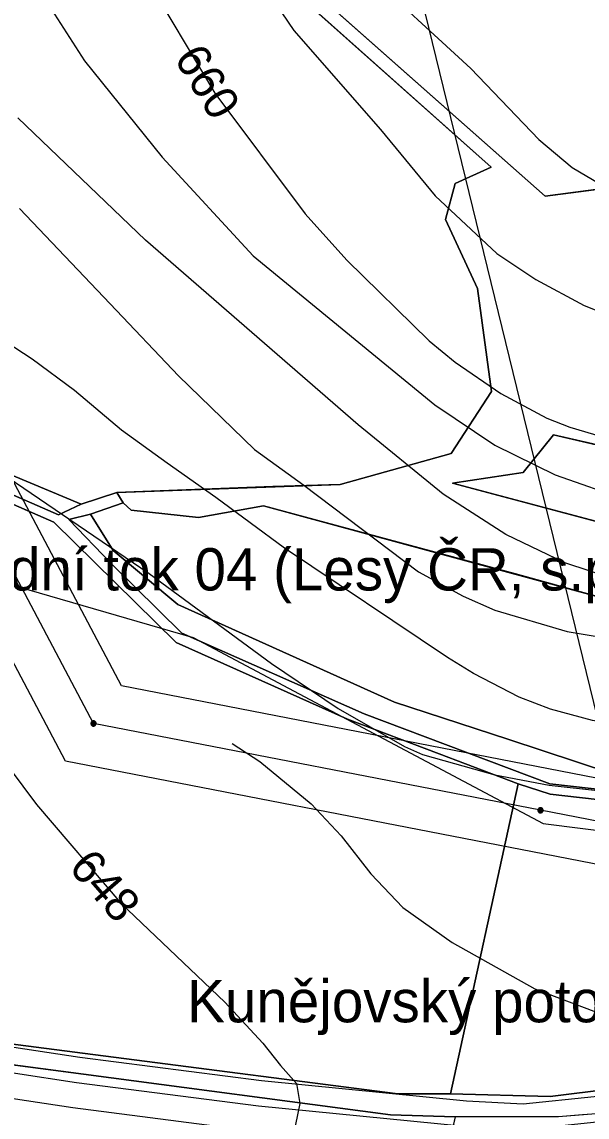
# Model space of a CAD drawing. Extents: x -709418 to -703832, y -1161719 to -1157826.
# Drawn here: x -706607.7 to -706474.1, y -1160852.4 to -1160593.4 of the extents above; entities that cross this region are included whole.
import ezdxf

# ---------------------------------------------------------------- set-up
doc = ezdxf.new("R2010")
doc.units = 0
for name, color, linetype in [('102_obvod PÚ', 7, 'Continuous'), ('120_vrstevnice hlavní', 7, 'Continuous'), ('121_vrstevnice hlavní_popis', 7, 'Continuous'), ('122_vrstevnice základní', 7, 'Continuous'), ('124_vrstevnice doplňková', 7, 'Continuous'), ('206_TTP_KN', 7, 'Continuous'), ('207_lesní pozemek_KN', 7, 'Continuous'), ('208_vodní plocha_KN', 7, 'Continuous'), ('210_ostatní plocha_KN', 7, 'Continuous'), ('501_vodní tok', 7, 'Continuous'), ('502_vodní tok_popis', 7, 'Continuous'), ('514 odvodnění - LPIS', 7, 'Continuous'), ('705_el VN nadzemní_E.ON', 7, 'Continuous'), ('723_radioreléová trasa_UAP', 7, 'Continuous'), ('735_OP sítí TI', 7, 'Continuous')]:
    doc.layers.add(name, color=color, linetype=linetype)

# ---------------------------------------------------------------- blocks, each defined once
blk = doc.blocks.new('Elektro - Implicitní$0$VN4601')
for points in [[(1.23, 0), (1.22, 0.13), (1.2, 0.26), (1.17, 0.38), (1.12, 0.5), (1.06, 0.61), (0.99, 0.72), (0.91, 0.82), (0.82, 0.91), (0.72, 0.99), (0.61, 1.06), (0.5, 1.12), (0.38, 1.17), (0.26, 1.2), (0.13, 1.22), (0, 1.23), (-0.13, 1.22), (-0.26, 1.2), (-0.38, 1.17), (-0.5, 1.12), (-0.61, 1.06), (-0.72, 0.99), (-0.82, 0.91), (-0.91, 0.82), (-0.99, 0.72), (-1.06, 0.61), (-1.12, 0.5), (-1.17, 0.38), (-1.2, 0.26), (-1.22, 0.13), (-1.23, 0), (-1.22, -0.13), (-1.2, -0.26), (-1.17, -0.38), (-1.12, -0.5), (-1.06, -0.61), (-0.99, -0.72), (-0.91, -0.82), (-0.82, -0.91), (-0.72, -0.99), (-0.61, -1.06), (-0.5, -1.12), (-0.38, -1.17), (-0.26, -1.2), (-0.13, -1.22), (0, -1.23), (0.13, -1.22), (0.26, -1.2), (0.38, -1.17), (0.5, -1.12), (0.61, -1.06), (0.72, -0.99), (0.82, -0.91), (0.91, -0.82), (0.99, -0.72), (1.06, -0.61), (1.12, -0.5), (1.17, -0.38), (1.2, -0.26), (1.22, -0.13), (1.23, 0)], [(0.92, 0), (0.92, 0.1), (0.9, 0.19), (0.88, 0.28), (0.84, 0.37), (0.8, 0.46), (0.75, 0.54), (0.68, 0.62), (0.62, 0.68), (0.54, 0.74), (0.46, 0.8), (0.37, 0.84), (0.28, 0.88), (0.19, 0.9), (0.1, 0.92), (0, 0.92), (-0.1, 0.92), (-0.19, 0.9), (-0.28, 0.88), (-0.37, 0.84), (-0.46, 0.8), (-0.54, 0.74), (-0.62, 0.68), (-0.68, 0.62), (-0.75, 0.54), (-0.8, 0.46), (-0.84, 0.37), (-0.88, 0.28), (-0.9, 0.19), (-0.92, 0.1), (-0.92, 0), (-0.92, -0.1), (-0.9, -0.19), (-0.88, -0.29), (-0.84, -0.38), (-0.8, -0.46), (-0.75, -0.54), (-0.68, -0.62), (-0.62, -0.69), (-0.54, -0.75), (-0.46, -0.8), (-0.37, -0.84), (-0.28, -0.88), (-0.19, -0.9), (-0.1, -0.92), (0, -0.92), (0.1, -0.92), (0.19, -0.9), (0.28, -0.88), (0.37, -0.84), (0.46, -0.8), (0.54, -0.75), (0.62, -0.69), (0.68, -0.62), (0.75, -0.54), (0.8, -0.46), (0.84, -0.38), (0.88, -0.29), (0.9, -0.19), (0.92, -0.1), (0.92, 0)], [(0.61, 0), (0.61, 0.06), (0.6, 0.13), (0.58, 0.19), (0.56, 0.25), (0.53, 0.31), (0.5, 0.36), (0.46, 0.41), (0.41, 0.46), (0.36, 0.5), (0.31, 0.53), (0.25, 0.56), (0.19, 0.58), (0.13, 0.6), (0.06, 0.61), (0, 0.61), (-0.06, 0.61), (-0.13, 0.6), (-0.19, 0.58), (-0.25, 0.56), (-0.31, 0.53), (-0.36, 0.5), (-0.41, 0.46), (-0.46, 0.41), (-0.5, 0.36), (-0.53, 0.31), (-0.56, 0.25), (-0.58, 0.19), (-0.6, 0.13), (-0.61, 0.06), (-0.61, 0), (-0.61, -0.07), (-0.6, -0.13), (-0.58, -0.19), (-0.56, -0.25), (-0.53, -0.31), (-0.5, -0.36), (-0.46, -0.41), (-0.41, -0.46), (-0.36, -0.5), (-0.31, -0.53), (-0.25, -0.56), (-0.19, -0.58), (-0.13, -0.6), (-0.06, -0.61), (0, -0.61), (0.06, -0.61), (0.13, -0.6), (0.19, -0.58), (0.25, -0.56), (0.31, -0.53), (0.36, -0.5), (0.41, -0.46), (0.46, -0.41), (0.5, -0.36), (0.53, -0.31), (0.56, -0.25), (0.58, -0.19), (0.6, -0.13), (0.61, -0.06), (0.61, 0)], [(0.31, 0), (0.31, 0.03), (0.3, 0.06), (0.29, 0.09), (0.28, 0.12), (0.27, 0.15), (0.25, 0.18), (0.23, 0.21), (0.21, 0.23), (0.18, 0.25), (0.15, 0.27), (0.12, 0.28), (0.09, 0.29), (0.06, 0.3), (0.03, 0.31), (0, 0.31), (-0.03, 0.31), (-0.06, 0.3), (-0.09, 0.29), (-0.12, 0.28), (-0.15, 0.27), (-0.18, 0.25), (-0.21, 0.23), (-0.23, 0.21), (-0.25, 0.18), (-0.27, 0.15), (-0.28, 0.12), (-0.29, 0.09), (-0.3, 0.06), (-0.31, 0.03), (-0.31, 0), (-0.31, -0.03), (-0.3, -0.06), (-0.29, -0.1), (-0.28, -0.13), (-0.27, -0.15), (-0.25, -0.18), (-0.23, -0.21), (-0.21, -0.23), (-0.18, -0.25), (-0.15, -0.27), (-0.12, -0.28), (-0.09, -0.29), (-0.06, -0.3), (-0.03, -0.31), (0, -0.31), (0.03, -0.31), (0.06, -0.3), (0.09, -0.29), (0.12, -0.28), (0.15, -0.27), (0.18, -0.25), (0.21, -0.23), (0.23, -0.21), (0.25, -0.18), (0.27, -0.15), (0.28, -0.13), (0.29, -0.1), (0.3, -0.06), (0.31, -0.03), (0.31, 0)]]:
    blk.add_lwpolyline(points)

msp = doc.modelspace()

# ---------------------------------------------------------------- linework, layer by layer
at = {"layer": '102_obvod PÚ'}
for points in [[(-706585.3, -1160704.67), (-706532.43, -1160702.83), (-706506.18, -1160695.47), (-706496.69, -1160680.82), (-706499.95, -1160656.47), (-706507.52, -1160640.12), (-706505.26, -1160631.63), (-706496.76, -1160627.81), (-706561.66, -1160569.9)], [(-706561.66, -1160569.9), (-706496.76, -1160627.81), (-706505.26, -1160631.63), (-706507.52, -1160640.12), (-706499.95, -1160656.47), (-706496.69, -1160680.82), (-706506.18, -1160695.47), (-706532.43, -1160702.83), (-706585.3, -1160704.67)], [(-706537.25, -1160587.47), (-706483.95, -1160634.67), (-706437.33, -1160628.53), (-706435.81, -1160625.24), (-706446.25, -1160609.53), (-706405.71, -1160604.59), (-706388.94, -1160609.69), (-706404.23, -1160630.57), (-706399.98, -1160652.01), (-706415.48, -1160655.34), (-706426.59, -1160662.98), (-706421.4, -1160677.36), (-706353.84, -1160665.92), (-706212.91, -1160642.8), (-706210.48, -1160628.13), (-706190.31, -1160626.07), (-706166.67, -1160638.53), (-706094.84, -1160616.38)], [(-706094.84, -1160616.38), (-706166.67, -1160638.53), (-706190.31, -1160626.07), (-706210.48, -1160628.13), (-706212.91, -1160642.8), (-706353.84, -1160665.92), (-706421.4, -1160677.36), (-706426.59, -1160662.98), (-706415.48, -1160655.34), (-706399.98, -1160652.01), (-706404.23, -1160630.57), (-706388.94, -1160609.69), (-706405.71, -1160604.59), (-706446.25, -1160609.53), (-706435.81, -1160625.24), (-706437.33, -1160628.53), (-706483.95, -1160634.67), (-706537.25, -1160587.47)], [(-706078.84, -1160616.17), (-706172.32, -1160644.88), (-706186.83, -1160645.94), (-706180.3, -1160673), (-706202.87, -1160669.67), (-706205.21, -1160662.52), (-706201.46, -1160647.52), (-706309.32, -1160662.59), (-706417.2, -1160682.29), (-706421.21, -1160690.13), (-706440.11, -1160691.54), (-706447.05, -1160699.18), (-706482.01, -1160691.05), (-706489.16, -1160699.96), (-706505.86, -1160702.51), (-706452.64, -1160716.67), (-706455.75, -1160733.65), (-706550.59, -1160707.82), (-706565.95, -1160710.65), (-706581.87, -1160708.88), (-706583.78, -1160707.11), (-706585.3, -1160704.67)], [(-706585.3, -1160704.67), (-706583.78, -1160707.11), (-706581.87, -1160708.88), (-706565.95, -1160710.65), (-706550.59, -1160707.82), (-706455.75, -1160733.65), (-706452.64, -1160716.67), (-706505.86, -1160702.51), (-706489.16, -1160699.96), (-706482.01, -1160691.05), (-706447.05, -1160699.18), (-706440.11, -1160691.54), (-706421.21, -1160690.13), (-706417.2, -1160682.29), (-706309.32, -1160662.59), (-706201.46, -1160647.52), (-706205.21, -1160662.52), (-706202.87, -1160669.67), (-706180.3, -1160673), (-706186.83, -1160645.94), (-706172.32, -1160644.88), (-706078.84, -1160616.17)], [(-706132.64, -1160763.73), (-706186.11, -1160775.01), (-706211.95, -1160782.93), (-706228.36, -1160784.79), (-706284.52, -1160780.59), (-706285.11, -1160766.44), (-706317.29, -1160776.61), (-706343.44, -1160778.04), (-706343.3, -1160802.68), (-706355.36, -1160805.32), (-706354.93, -1160815.6), (-706354.36, -1160827.87), (-706344.72, -1160825.16), (-706297.34, -1160821.34), (-706288.53, -1160820.63), (-706288.78, -1160824.8), (-706344.65, -1160829.16), (-706368.79, -1160838.42), (-706446.04, -1160849.6), (-706472.94, -1160851.67), (-706480.86, -1160852.31), (-706505.26, -1160852.31), (-706520.68, -1160919.75)]]:
    msp.add_lwpolyline(points, dxfattribs=at)
at = {"layer": '120_vrstevnice hlavní'}
for points in [[(-706575.65, -1160587.5), (-706562.11, -1160610.3), (-706540.74, -1160638.8), (-706530.91, -1160649.77), (-706511.38, -1160668.87), (-706505.26, -1160673.86), (-706494.43, -1160681.27), (-706483.6, -1160687.11), (-706478.18, -1160689.25), (-706461.94, -1160694.09), (-706451.11, -1160695.09), (-706445.6, -1160694.97), (-706439.71, -1160694.09), (-706430.47, -1160691.96), (-706421.75, -1160688.53), (-706396.39, -1160674.85), (-706357.77, -1160650.77), (-706347.51, -1160645.93), (-706341.96, -1160643.93)], [(-706620.39, -1160694.8), (-706577.64, -1160723.87), (-706548.72, -1160745.1), (-706532.9, -1160755.79), (-706517.22, -1160764.77), (-706512.95, -1160766.62), (-706495.85, -1160771.46), (-706483.03, -1160773.89), (-706470.2, -1160775.31), (-706434.29, -1160775.6), (-706385.85, -1160773.03), (-706367.61, -1160773.6), (-706350.51, -1160776.17), (-706341.96, -1160778.3)]]:
    msp.add_lwpolyline(points, dxfattribs=at)
at = {"layer": '122_vrstevnice základní'}
for points in [[(-706558.26, -1160573.54), (-706543.44, -1160595.48), (-706522.93, -1160618.85), (-706509.96, -1160634.53), (-706495.42, -1160648.21), (-706486.16, -1160654.33), (-706474.76, -1160660.46), (-706457.66, -1160667.3), (-706449.11, -1160669.44), (-706437.71, -1160670.72), (-706431.73, -1160670.44), (-706425.46, -1160669.3), (-706416.05, -1160665.88), (-706403.37, -1160657.04), (-706373.45, -1160630.25), (-706362.67, -1160623.11), (-706348.8, -1160618.14), (-706339.39, -1160615.86)], [(-706527.63, -1160580.38), (-706501.55, -1160604.46), (-706485.45, -1160621.28), (-706477.61, -1160627.83), (-706466.21, -1160634.53), (-706450.25, -1160641.22), (-706445.69, -1160642.51), (-706438.85, -1160643.36), (-706429.14, -1160643.21), (-706423.59, -1160642.35), (-706417.76, -1160640.51), (-706412.35, -1160637.8), (-706407.79, -1160634.24), (-706401.38, -1160626.26), (-706396.96, -1160617.71), (-706391.12, -1160609.16), (-706386.46, -1160604.18), (-706382.28, -1160600.9), (-706376.44, -1160597.05), (-706366.47, -1160592.63)], [(-706605, -1160583.8), (-706592.89, -1160602.61), (-706574.51, -1160625.41), (-706552.99, -1160648.78), (-706510.1, -1160683.97), (-706495.85, -1160693.52), (-706481.6, -1160700.5), (-706464.5, -1160706.49), (-706453.1, -1160708.34), (-706444.27, -1160708.34), (-706431.73, -1160707.2), (-706416.05, -1160704.35), (-706400.38, -1160699.93), (-706372.17, -1160689.81), (-706341.1, -1160676.99)], [(-706334.03, -1160702.99), (-706343.67, -1160705.06), (-706365.61, -1160711.47), (-706379.58, -1160716.18), (-706411.49, -1160724.3), (-706421.47, -1160726.29), (-706433.44, -1160727.86), (-706438.09, -1160728.08), (-706447.4, -1160728.15), (-706453.39, -1160727.72), (-706467.35, -1160725.3), (-706479.32, -1160721.31), (-706493.29, -1160714.61), (-706508.11, -1160705.06), (-706528.2, -1160688.68), (-706578.5, -1160645.07), (-706608.71, -1160616.15)], [(-706608.28, -1160637.52), (-706586.87, -1160660.09), (-706570.66, -1160677.13), (-706552.71, -1160694.52), (-706541.02, -1160702.93), (-706513.95, -1160723.44), (-706503.38, -1160729.2), (-706495.85, -1160732.56), (-706478.75, -1160737.55), (-706465.07, -1160739.83), (-706443.41, -1160741.11), (-706426.84, -1160740.36), (-706418.9, -1160739.55), (-706375.59, -1160734.7), (-706357.35, -1160731), (-706339.11, -1160728.43)], [(-706324, -1160754.51), (-706361.62, -1160750.52), (-706371.9, -1160750.02), (-706383.85, -1160750.23), (-706399.24, -1160752.23), (-706438.57, -1160758.93), (-706452.25, -1160760.06), (-706464.22, -1160759.92), (-706472.77, -1160758.64), (-706482.69, -1160755.91), (-706490.15, -1160753.08), (-706500.92, -1160747.51), (-706507.11, -1160743.68), (-706545.58, -1160717.89), (-706561.83, -1160705.92), (-706573.37, -1160697.8), (-706584.2, -1160689.96), (-706595.31, -1160680.55), (-706605.29, -1160673.14), (-706656.59, -1160639.66)], [(-706617.01, -1160761.43), (-706604.29, -1160778.45), (-706584.34, -1160801.82), (-706559.69, -1160825.19), (-706550.71, -1160834.87), (-706546.58, -1160840.15)], [(-706546.58, -1160840.15), (-706542.78, -1160844.42), (-706541.99, -1160849.16), (-706544.64, -1160862.2), (-706548.72, -1160880.47), (-706555.13, -1160885.17), (-706561.4, -1160887.88), (-706570.8, -1160889.88), (-706580.21, -1160890.45), (-706602.15, -1160889.59), (-706664.85, -1160882.9), (-706677.29, -1160882.43), (-706689.93, -1160882.9), (-706702.47, -1160884.32), (-706718.14, -1160887.31), (-706743.22, -1160894.01), (-706765.17, -1160899), (-706783.97, -1160900.28), (-706800.73, -1160898.5)]]:
    msp.add_lwpolyline(points, dxfattribs=at)
at = {"layer": '124_vrstevnice doplňková'}
msp.add_lwpolyline([(-706558.01, -1160764.02), (-706551.42, -1160768.33), (-706539.31, -1160778.3), (-706532.19, -1160785.86), (-706525.21, -1160794.83), (-706517.65, -1160802.81), (-706505.97, -1160811.08), (-706486.45, -1160822.05), (-706472.48, -1160827.32), (-706461.67, -1160830.53), (-706453.13, -1160833.79), (-706449.11, -1160836.3), (-706442.42, -1160840.72), (-706436.19, -1160847.18), (-706433.82, -1160851.92), (-706434.25, -1160859.11)], dxfattribs=at)
at = {"layer": '206_TTP_KN'}
for p, q in [((-706561.66, -1160569.9), (-706496.76, -1160627.81)), ((-706496.76, -1160627.81), (-706505.26, -1160631.63)), ((-706505.26, -1160631.63), (-706507.52, -1160640.12)), ((-706507.52, -1160640.12), (-706499.95, -1160656.47)), ((-706499.95, -1160656.47), (-706496.69, -1160680.82)), ((-706593.72, -1160707.46), (-706663.56, -1160678.25)), ((-706496.69, -1160680.82), (-706506.18, -1160695.47)), ((-706660.96, -1160685.35), (-706600.17, -1160711.68)), ((-706489.16, -1160699.96), (-706482.01, -1160691.05)), ((-706482.01, -1160691.05), (-706447.05, -1160699.18)), ((-706506.18, -1160695.47), (-706532.43, -1160702.83)), ((-706505.86, -1160702.51), (-706489.16, -1160699.96)), ((-706548.36, -1160703.25), (-706585.3, -1160704.67)), ((-706532.43, -1160702.83), (-706548.36, -1160703.25)), ((-706452.64, -1160716.67), (-706505.86, -1160702.51)), ((-706585.3, -1160704.67), (-706593.72, -1160707.46)), ((-706591.5, -1160709.84), (-706583.78, -1160707.11)), ((-706583.78, -1160707.11), (-706581.87, -1160708.88)), ((-706565.95, -1160710.65), (-706550.59, -1160707.82)), ((-706550.59, -1160707.82), (-706491, -1160723.96)), ((-706586.15, -1160718.38), (-706591.5, -1160709.84)), ((-706581.87, -1160708.88), (-706565.95, -1160710.65)), ((-706600.17, -1160711.68), (-706571.25, -1160740.13)), ((-706570.86, -1160731.19), (-706586.15, -1160718.38)), ((-706491, -1160723.96), (-706455.75, -1160733.65)), ((-706519.64, -1160754.25), (-706570.86, -1160731.19)), ((-706571.25, -1160740.13), (-706530.7, -1160758.32)), ((-706492.81, -1160763.05), (-706519.64, -1160754.25)), ((-706530.7, -1160758.32), (-706509.04, -1160766.53)), ((-706461.39, -1160773.42), (-706492.81, -1160763.05)), ((-706509.04, -1160766.53), (-706490.36, -1160773.6)), ((-706490.36, -1160773.6), (-706506.4, -1160846.9)), ((-706586.02, -1160838.2), (-706621.71, -1160833.58)), ((-706635.46, -1160836.75), (-706593.13, -1160842.2)), ((-706518.79, -1160846.9), (-706586.02, -1160838.2)), ((-706593.13, -1160842.2), (-706520.52, -1160851.82)), ((-706506.4, -1160846.9), (-706518.79, -1160846.9)), ((-706505.26, -1160852.31), (-706520.68, -1160919.75)), ((-706520.52, -1160851.82), (-706505.26, -1160852.31))]:
    msp.add_line(p, q, dxfattribs=at)
msp.add_lwpolyline([(-706094.84, -1160616.38), (-706166.67, -1160638.53), (-706190.31, -1160626.07), (-706210.48, -1160628.13), (-706212.91, -1160642.8), (-706353.84, -1160665.92), (-706421.4, -1160677.36), (-706426.59, -1160662.98), (-706415.48, -1160655.34), (-706399.98, -1160652.01), (-706404.23, -1160630.57), (-706388.94, -1160609.69), (-706405.71, -1160604.59), (-706446.25, -1160609.53), (-706435.81, -1160625.24), (-706437.33, -1160628.53), (-706483.95, -1160634.67), (-706537.25, -1160587.47)], dxfattribs=at)
at = {"layer": '207_lesní pozemek_KN'}
for p, q in [((-706496.76, -1160627.81), (-706561.66, -1160569.9)), ((-706537.25, -1160587.47), (-706483.95, -1160634.67)), ((-706505.26, -1160631.63), (-706496.76, -1160627.81)), ((-706483.95, -1160634.67), (-706437.33, -1160628.53)), ((-706507.52, -1160640.12), (-706505.26, -1160631.63)), ((-706499.95, -1160656.47), (-706507.52, -1160640.12)), ((-706496.69, -1160680.82), (-706499.95, -1160656.47)), ((-706506.18, -1160695.47), (-706496.69, -1160680.82)), ((-706482.01, -1160691.05), (-706489.16, -1160699.96)), ((-706447.05, -1160699.18), (-706482.01, -1160691.05)), ((-706532.43, -1160702.83), (-706506.18, -1160695.47)), ((-706489.16, -1160699.96), (-706505.86, -1160702.51)), ((-706585.3, -1160704.67), (-706548.36, -1160703.25)), ((-706548.36, -1160703.25), (-706532.43, -1160702.83)), ((-706505.86, -1160702.51), (-706452.64, -1160716.67)), ((-706583.78, -1160707.11), (-706585.3, -1160704.67)), ((-706581.87, -1160708.88), (-706583.78, -1160707.11)), ((-706550.59, -1160707.82), (-706565.95, -1160710.65)), ((-706491, -1160723.96), (-706550.59, -1160707.82)), ((-706565.95, -1160710.65), (-706581.87, -1160708.88)), ((-706455.75, -1160733.65), (-706491, -1160723.96))]:
    msp.add_line(p, q, dxfattribs=at)
at = {"layer": '208_vodní plocha_KN'}
for p, q in [((-706621.71, -1160833.58), (-706586.02, -1160838.2)), ((-706593.13, -1160842.2), (-706635.46, -1160836.75)), ((-706586.02, -1160838.2), (-706518.79, -1160846.9)), ((-706482.83, -1160847.47), (-706392.37, -1160836.66)), ((-706520.52, -1160851.82), (-706593.13, -1160842.2)), ((-706518.79, -1160846.9), (-706506.4, -1160846.9)), ((-706506.4, -1160846.9), (-706482.83, -1160847.47)), ((-706505.26, -1160852.31), (-706520.52, -1160851.82)), ((-706480.86, -1160852.31), (-706505.26, -1160852.31)), ((-706475.18, -1160851.85), (-706480.86, -1160852.31)), ((-706472.94, -1160851.67), (-706475.18, -1160851.85))]:
    msp.add_line(p, q, dxfattribs=at)
at = {"layer": '210_ostatní plocha_KN'}
for p, q in [((-706663.56, -1160678.25), (-706593.72, -1160707.46)), ((-706661.67, -1160682.8), (-706599.03, -1160709.98)), ((-706599.03, -1160709.98), (-706661.67, -1160682.8)), ((-706600.17, -1160711.68), (-706660.96, -1160685.35)), ((-706593.72, -1160707.46), (-706585.3, -1160704.67)), ((-706585.3, -1160704.67), (-706583.78, -1160707.11)), ((-706599.03, -1160709.98), (-706593.72, -1160707.46)), ((-706593.72, -1160707.46), (-706599.03, -1160709.98)), ((-706583.78, -1160707.11), (-706591.5, -1160709.84)), ((-706591.5, -1160709.84), (-706596.59, -1160711.11)), ((-706596.59, -1160711.11), (-706591.5, -1160709.84)), ((-706596.59, -1160711.11), (-706586.61, -1160721.51)), ((-706586.61, -1160721.51), (-706596.59, -1160711.11)), ((-706591.5, -1160709.84), (-706586.15, -1160718.38)), ((-706571.25, -1160740.13), (-706600.17, -1160711.68)), ((-706586.15, -1160718.38), (-706570.86, -1160731.19)), ((-706586.61, -1160721.51), (-706569.91, -1160738)), ((-706569.91, -1160738), (-706586.61, -1160721.51)), ((-706570.86, -1160731.19), (-706519.64, -1160754.25)), ((-706569.91, -1160738), (-706526.76, -1160757.02)), ((-706526.76, -1160757.02), (-706569.91, -1160738)), ((-706530.7, -1160758.32), (-706571.25, -1160740.13)), ((-706519.64, -1160754.25), (-706492.81, -1160763.05)), ((-706526.76, -1160757.02), (-706482.86, -1160773.55)), ((-706482.86, -1160773.55), (-706526.76, -1160757.02)), ((-706509.04, -1160766.53), (-706530.7, -1160758.32)), ((-706492.81, -1160763.05), (-706461.39, -1160773.42)), ((-706490.36, -1160773.6), (-706509.04, -1160766.53)), ((-706482.86, -1160773.55), (-706424.8, -1160780.15)), ((-706424.8, -1160780.15), (-706482.86, -1160773.55)), ((-706506.4, -1160846.9), (-706490.36, -1160773.6)), ((-706482.83, -1160776.06), (-706490.36, -1160773.6)), ((-706490.36, -1160773.6), (-706482.83, -1160776.06)), ((-706424.8, -1160782.5), (-706482.83, -1160776.06)), ((-706482.83, -1160776.06), (-706424.8, -1160782.5)), ((-706392.37, -1160836.66), (-706482.83, -1160847.47)), ((-706482.83, -1160847.47), (-706506.4, -1160846.9))]:
    msp.add_line(p, q, dxfattribs=at)
at = {"layer": '501_vodní tok'}
msp.add_lwpolyline([(-706294.74, -1160832), (-706344.96, -1160836.67), (-706361.92, -1160838.95), (-706380.23, -1160840.97), (-706402.58, -1160842.99), (-706419.81, -1160844.75), (-706434.62, -1160847.79), (-706456.43, -1160852.08), (-706471.78, -1160853.59), (-706489.01, -1160855.36), (-706503.02, -1160854.6), (-706551.76, -1160849.8), (-706594.84, -1160844.25), (-706638.19, -1160837.68), (-706729.87, -1160806.74), (-706754.65, -1160798.66), (-706775.37, -1160792.42), (-706776.87, -1160792.14)], dxfattribs=at)
at = {"layer": '514 odvodnění - LPIS'}
msp.add_lwpolyline([(-706863.97, -1160871.89), (-706791.27, -1160822.65), (-706735.19, -1160778.33), (-706748.47, -1160726.66), (-706643.11, -1160716.97), (-706567.25, -1160738.96), (-706484.44, -1160782.97), (-706418.79, -1160791.25), (-706025.59, -1160715.24)], dxfattribs=at)
at = {"layer": '705_el VN nadzemní_E.ON'}
msp.add_lwpolyline([(-706126.79, -1160947.26), (-706166.94, -1160904.58), (-706239.08, -1160827.82), (-706352.93, -1160805.53), (-706485.08, -1160779.84), (-706590.79, -1160759.31), (-706626.96, -1160690.96), (-706657.04, -1160633.68)], dxfattribs=at)
at = {"layer": '723_radioreléová trasa_UAP'}
msp.add_lwpolyline([(-707182.2, -1157850.62), (-706271.36, -1161577.76)], dxfattribs=at)
at = {"layer": '735_OP sítí TI'}
for points in [[(-706119.51, -1160940.41), (-706159.66, -1160897.73), (-706234, -1160818.62), (-706351.01, -1160795.71), (-706483.17, -1160770.02), (-706584.19, -1160750.4), (-706618.11, -1160686.3), (-706648.19, -1160629.03)], [(-706134.08, -1160954.11), (-706174.22, -1160911.43), (-706244.16, -1160837.01), (-706354.84, -1160815.34), (-706486.99, -1160789.66), (-706597.39, -1160768.21), (-706635.81, -1160695.62), (-706665.89, -1160638.33)], [(-706294.18, -1160837.97), (-706344.28, -1160842.63), (-706361.19, -1160844.9), (-706379.63, -1160846.94), (-706402, -1160848.96), (-706418.9, -1160850.69), (-706433.44, -1160853.67), (-706455.56, -1160858.02), (-706471.18, -1160859.56), (-706488.87, -1160861.38), (-706503.47, -1160860.59), (-706552.43, -1160855.77), (-706595.67, -1160850.19), (-706639.61, -1160843.53), (-706731.76, -1160812.44), (-706756.44, -1160804.39), (-706776.8, -1160798.25), (-706777.98, -1160798.03)], [(-706295.29, -1160826.03), (-706345.63, -1160830.71), (-706362.65, -1160832.99), (-706380.83, -1160835), (-706403.16, -1160837.01), (-706420.72, -1160838.82), (-706435.8, -1160841.9), (-706457.31, -1160846.14), (-706472.38, -1160847.62), (-706489.16, -1160849.34), (-706502.56, -1160848.62), (-706551.08, -1160843.84), (-706594.01, -1160838.31), (-706636.77, -1160831.83), (-706727.98, -1160801.05), (-706728.04, -1160801.03)]]:
    msp.add_lwpolyline(points, dxfattribs=at)

# ---------------------------------------------------------------- block references
at = {"layer": '705_el VN nadzemní_E.ON', "xscale": 0.49999999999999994, "yscale": 0.5000000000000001, "rotation": -11.430305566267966}
for p in [(-706590.79, -1160759.31), (-706485.08, -1160779.84)]:
    msp.add_blockref('Elektro - Implicitní$0$VN4601', p, dxfattribs=at)

# ---------------------------------------------------------------- texts
at = {"layer": '121_vrstevnice hlavní_popis'}
for s, rotation, p in [('660', 301.6809, (-706571.9, -1160602.04)), ('648', 311.1029, (-706596.9, -1160793.52))]:
    msp.add_text(s, height=8, rotation=rotation, dxfattribs=at).set_placement(p)
at = {"layer": '502_vodní tok_popis'}
for s, p in [('Bezejmenný vodní tok 04 (Lesy ČR, s.p.)', (-706702.19, -1160727.87)), ('Kunějovský potok (Lesy ČR, s.p.)', (-706568.63, -1160829.97))]:
    msp.add_text(s, height=10, dxfattribs=at).set_placement(p)

doc.saveas('drawing.dxf')
